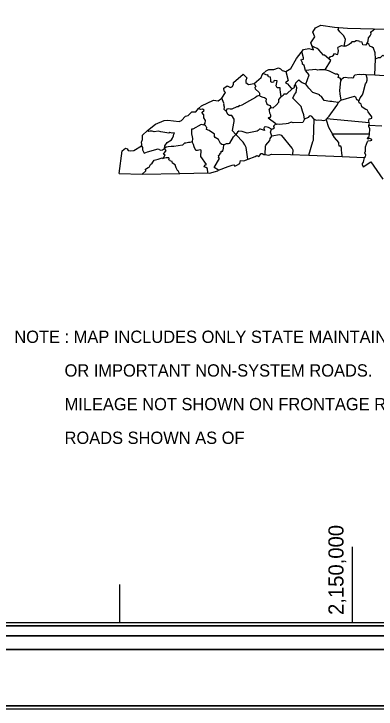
# Model space of a CAD drawing. Extents: x 5197761 to 5514561, y 1890130 to 2080942.
# Drawn here: x 5366240 to 5381799, y 1890130 to 1920005 of the extents above; entities that cross this region are included whole.
import ezdxf

# ---------------------------------------------------------------- set-up
doc = ezdxf.new("R2010")
doc.units = 0
for name, color, linetype in [('Map Preparation Base Location CELL', 7, 'Continuous'), ('Map Preparation Base Note CELL', 7, 'Continuous'), ('Map Preparation Base StatePlane Tick Label', 7, 'Continuous'), ('Map Preparation Base StatePlane Tick Mark', 7, 'Continuous'), ('Map Preparation Border Antique Large Shape', 7, 'Continuous'), ('Map Preparation Border Antique Small Shape', 7, 'Continuous'), ('Map Preparation Border Black Inside Shape', 7, 'Continuous'), ('Map Preparation Border Black Middle Shape', 7, 'Continuous'), ('Map Preparation Border Black Outside Shape', 7, 'Continuous')]:
    doc.layers.add(name, color=color, linetype=linetype)

msp = doc.modelspace()

# ---------------------------------------------------------------- linework, layer by layer
at = {"layer": 'Map Preparation Base Location CELL'}
for p, q in [((5379605, 1917603), (5379848, 1918008)), ((5379848, 1918008), (5379766, 1918070)), ((5381750, 1917370), (5381374, 1917386)), ((5380190, 1916200), (5380283, 1916298)), ((5379651, 1915448), (5379672, 1915498)), ((5381508, 1915324), (5379672, 1915498)), ((5382052, 1915179), (5381491, 1915215)), ((5381510, 1914842), (5379926, 1914837))]:
    msp.add_line(p, q, dxfattribs=at)
for points in [[(5370768, 1913142), (5370889, 1914119), (5371028, 1914231), (5371106, 1914204), (5371152, 1914141), (5371253, 1914120), (5371390, 1914139), (5371715, 1914331), (5371715, 1914331), (5371741, 1914395), (5371716, 1914486), (5371769, 1914606), (5371764, 1914789), (5371974, 1915000), (5372320, 1915270), (5372697, 1915427), (5372849, 1915443), (5373340, 1915383), (5373442, 1915427), (5373610, 1915610), (5373728, 1915643), (5373880, 1915794), (5374058, 1915799), (5374176, 1915940), (5374301, 1916048), (5374813, 1916291), (5375013, 1916269), (5375170, 1916377), (5375332, 1916626), (5375272, 1916688), (5375262, 1916818), (5375396, 1916915), (5375542, 1916839), (5375629, 1916888), (5375677, 1916980), (5375677, 1917061), (5376090, 1917412), (5376252, 1917255), (5376203, 1917147), (5376208, 1917050), (5376316, 1916974), (5376565, 1917012), (5376856, 1917277), (5376905, 1917390), (5376953, 1917450), (5377072, 1917563), (5377185, 1917612), (5377407, 1917617), (5377601, 1917682), (5377698, 1917639), (5377758, 1917568), (5377920, 1917531), (5378141, 1917660), (5378373, 1918092), (5378675, 1918481), (5378913, 1918524), (5379107, 1918460), (5378999, 1918762), (5379172, 1919021), (5379086, 1919216), (5379193, 1919410), (5379431, 1919518), (5380014, 1919432), (5380575, 1919389), (5384470, 1919293)], [(5380430, 1918621), (5380482, 1918902), (5380414, 1919061), (5380243, 1919230), (5380166, 1919332), (5380202, 1919417)], [(5381417, 1918753), (5381463, 1918841), (5381470, 1918975), (5381543, 1919059), (5381592, 1919142), (5381579, 1919203), (5381599, 1919245), (5381742, 1919360)], [(5379766, 1918070), (5379588, 1918226), (5379535, 1918238), (5379344, 1918460), (5379270, 1918520), (5379133, 1918580), (5379043, 1918639)], [(5379766, 1918070), (5379846, 1918180), (5379907, 1918189), (5379967, 1918225), (5380019, 1918298), (5380120, 1918266), (5380153, 1918274), (5380176, 1918334), (5380181, 1918428), (5380158, 1918553), (5380166, 1918574), (5380315, 1918651), (5380430, 1918621)], [(5381417, 1918753), (5381338, 1918657), (5381225, 1918669), (5381203, 1918794), (5381091, 1918807), (5381066, 1918828), (5380982, 1918845), (5380936, 1918843), (5380878, 1918798), (5380752, 1918808), (5380715, 1918750), (5380637, 1918685), (5380498, 1918620), (5380430, 1918621)], [(5381769, 1918078), (5381763, 1918331), (5381693, 1918526), (5381624, 1918582), (5381524, 1918615), (5381483, 1918707), (5381417, 1918753)], [(5378765, 1917567), (5378709, 1917781), (5378640, 1917840), (5378641, 1917908), (5378578, 1918011), (5378600, 1918062), (5378633, 1918044), (5378677, 1918060), (5378676, 1918114), (5378604, 1918389)], [(5381750, 1917370), (5381769, 1918078)], [(5381769, 1918078), (5381906, 1918133), (5381993, 1918129), (5382092, 1918236), (5382103, 1918220), (5382177, 1918195), (5382348, 1918178), (5382435, 1918147), (5382556, 1918250), (5382600, 1918234), (5382647, 1918213), (5382800, 1918225), (5382843, 1918210), (5382878, 1918168), (5382922, 1918157), (5383003, 1918153), (5383060, 1918135), (5383128, 1918075)], [(5378211, 1916798), (5377950, 1916561), (5377830, 1916551), (5377809, 1916500), (5377723, 1916436), (5377704, 1916528), (5377699, 1916650), (5377685, 1916746), (5377684, 1916831), (5377552, 1916831), (5377513, 1916908), (5377544, 1917128), (5377455, 1917140), (5377408, 1917129), (5377396, 1917077), (5377335, 1917063), (5377283, 1917083), (5377278, 1917174), (5377262, 1917288), (5377173, 1917305), (5377144, 1917389), (5377101, 1917373), (5376954, 1917450)], [(5377921, 1917532), (5378019, 1917138), (5377905, 1917042), (5377995, 1917003), (5378139, 1916835), (5378211, 1916798)], [(5379605, 1917603), (5379372, 1917601), (5379275, 1917593), (5379209, 1917615), (5378765, 1917567)], [(5378776, 1916991), (5378930, 1917391), (5378765, 1917567)], [(5380293, 1917175), (5380261, 1917238), (5380167, 1917279), (5380193, 1917360), (5380128, 1917410), (5380052, 1917421), (5379796, 1917544), (5379605, 1917603)], [(5381374, 1917386), (5381259, 1917408), (5381164, 1917387), (5381075, 1917404), (5380883, 1917370), (5380846, 1917335), (5380819, 1917250), (5380799, 1917239), (5380737, 1917253), (5380632, 1917250), (5380498, 1917270), (5380405, 1917253), (5380293, 1917175), (5380273, 1917133), (5380232, 1916713), (5380242, 1916573), (5380283, 1916298)], [(5378333, 1916978), (5378347, 1917047), (5378484, 1917176), (5378575, 1917082), (5378626, 1917053), (5378776, 1916991)], [(5381052, 1916251), (5381115, 1916394), (5381209, 1916527), (5381248, 1916607), (5381346, 1917004), (5381382, 1917057), (5381412, 1917161), (5381416, 1917250), (5381374, 1917386)], [(5382365, 1917334), (5381750, 1917370)], [(5376566, 1917013), (5376637, 1916885), (5376595, 1916846), (5376597, 1916792), (5376778, 1916629), (5376797, 1916599), (5376791, 1916493)], [(5378211, 1916798), (5378290, 1916840), (5378291, 1916907), (5378333, 1916978)], [(5378718, 1915479), (5378695, 1915661), (5378634, 1915830), (5378577, 1916031), (5378229, 1916388), (5378300, 1916535), (5378363, 1916624), (5378401, 1916825), (5378333, 1916978)], [(5380190, 1916200), (5379967, 1916224), (5379902, 1916242), (5379811, 1916246), (5379562, 1916283), (5379448, 1916460), (5379372, 1916498), (5379375, 1916520), (5379087, 1916633), (5378905, 1916816), (5378776, 1916991)], [(5376791, 1916493), (5376693, 1916475), (5376612, 1916410), (5376361, 1916269), (5376032, 1916090), (5375964, 1916055), (5375920, 1916065), (5375867, 1916005), (5375822, 1916011), (5375600, 1915907), (5375532, 1915907), (5375466, 1915924), (5375382, 1915904), (5375361, 1915844)], [(5376791, 1916493), (5376814, 1916463), (5376935, 1916420), (5377008, 1916419), (5377045, 1916391), (5377075, 1916351), (5377066, 1916254), (5377106, 1916146), (5377158, 1916103), (5377244, 1916065), (5377273, 1915985)], [(5375361, 1915844), (5375296, 1915866), (5375272, 1915892), (5375281, 1915997), (5375254, 1916095), (5375269, 1916137), (5375264, 1916174), (5375174, 1916383)], [(5377273, 1915985), (5377375, 1915966), (5377508, 1916077), (5377623, 1916213)], [(5377623, 1916213), (5377616, 1916326), (5377723, 1916436)], [(5379672, 1915498), (5379784, 1915611), (5380112, 1916068), (5380190, 1916200)], [(5380283, 1916298), (5380877, 1916470), (5380919, 1916446), (5380956, 1916333), (5380994, 1916313), (5381052, 1916251)], [(5381508, 1915324), (5381491, 1915416), (5381507, 1915494), (5381567, 1915503), (5381615, 1915518), (5381617, 1915584), (5381463, 1915791), (5381422, 1915878), (5381356, 1915892), (5381240, 1915968), (5381193, 1916011), (5381155, 1916119), (5381075, 1916189), (5381052, 1916251)], [(5374397, 1915230), (5374457, 1915307), (5374477, 1915424), (5374402, 1915541), (5374401, 1915674), (5374319, 1915774), (5374346, 1915802), (5374405, 1915843), (5374413, 1915865), (5374341, 1915905), (5374254, 1915898), (5374168, 1915933)], [(5377496, 1915285), (5377168, 1915531), (5377198, 1915549), (5377244, 1915551), (5377281, 1915591), (5377280, 1915649), (5377230, 1915741), (5377213, 1915850), (5377200, 1915883), (5377273, 1915985)], [(5375779, 1914828), (5375624, 1914986), (5375642, 1915081), (5375705, 1915385), (5375695, 1915475), (5375595, 1915640), (5375505, 1915643), (5375424, 1915676), (5375361, 1915844)], [(5379144, 1915481), (5379038, 1915590), (5378983, 1915620), (5378923, 1915611), (5378883, 1915549), (5378718, 1915479)], [(5378718, 1915479), (5378657, 1915341), (5378234, 1915325), (5378144, 1915355), (5378017, 1915293), (5377938, 1915277), (5377774, 1915273), (5377644, 1915247), (5377583, 1915260), (5377522, 1915255), (5377496, 1915285)], [(5378909, 1913938), (5379079, 1914519), (5379107, 1914582), (5379144, 1915481)], [(5379144, 1915481), (5379228, 1915433), (5379342, 1915453), (5379465, 1915443), (5379543, 1915430), (5379651, 1915448)], [(5379651, 1915448), (5379754, 1915138), (5379865, 1914939), (5379926, 1914837)], [(5381491, 1915215), (5381512, 1915292), (5381508, 1915324)], [(5374397, 1915230), (5374287, 1915253), (5373932, 1915058), (5373869, 1915052), (5373865, 1914853), (5373903, 1914728), (5373916, 1914655), (5373902, 1914506)], [(5375257, 1914372), (5375178, 1914387), (5375117, 1914430), (5375032, 1914610), (5374891, 1914699), (5374860, 1914739), (5374855, 1914833), (5374624, 1915001), (5374516, 1915032), (5374527, 1915120), (5374499, 1915146), (5374475, 1915206), (5374397, 1915230)], [(5377305, 1915057), (5377171, 1915129), (5377069, 1915148), (5376995, 1915135), (5376975, 1915085), (5376992, 1915047), (5376999, 1914997), (5376834, 1915051), (5376789, 1915048), (5376740, 1914988), (5376691, 1914963), (5376264, 1914878), (5376049, 1914956), (5375907, 1914971), (5375841, 1914917), (5375779, 1914828)], [(5377315, 1914745), (5377272, 1914884), (5377269, 1914929), (5377305, 1915057)], [(5377305, 1915057), (5377360, 1915059), (5377432, 1915124), (5377411, 1915167), (5377411, 1915199), (5377496, 1915285)], [(5381510, 1914842), (5381532, 1915070), (5381493, 1915170), (5381491, 1915215)], [(5372704, 1914221), (5372724, 1914342), (5372817, 1914473), (5373003, 1914592), (5373052, 1914661), (5373101, 1914762), (5373110, 1914832), (5373144, 1914890), (5373136, 1914900), (5373039, 1914876), (5372939, 1914911), (5372891, 1914885), (5372546, 1914937), (5372451, 1914966), (5372262, 1914940), (5372175, 1914964), (5372094, 1914965), (5372039, 1914958), (5371958, 1914987)], [(5375257, 1914372), (5375370, 1914437), (5375465, 1914438), (5375512, 1914454), (5375670, 1914722), (5375779, 1914828)], [(5376290, 1913758), (5376215, 1914258), (5376160, 1914381), (5376085, 1914493), (5375779, 1914828)], [(5377029, 1913963), (5377048, 1914323), (5377068, 1914365), (5377227, 1914570), (5377252, 1914647), (5377315, 1914745)], [(5378227, 1913960), (5378241, 1914153), (5378199, 1914239), (5377744, 1914774), (5377644, 1914801), (5377315, 1914745)], [(5380344, 1913870), (5380328, 1914061), (5380306, 1914122), (5380309, 1914233), (5380277, 1914318), (5380218, 1914318), (5380204, 1914431), (5380203, 1914485), (5380018, 1914699), (5379926, 1914837)], [(5381292, 1913832), (5381338, 1913880), (5381359, 1913930), (5381320, 1914029), (5381345, 1914101), (5381343, 1914292), (5381433, 1914519), (5381465, 1914550), (5381580, 1914564), (5381609, 1914577), (5381614, 1914608), (5381560, 1914643), (5381507, 1914651), (5381458, 1914627), (5381436, 1914657), (5381445, 1914687), (5381497, 1914732), (5381510, 1914842)], [(5373902, 1914506), (5373794, 1914476), (5373736, 1914483), (5373621, 1914457), (5373562, 1914456), (5373477, 1914360), (5373115, 1914303), (5372994, 1914309), (5372861, 1914286), (5372783, 1914277), (5372704, 1914221)], [(5374568, 1913172), (5374553, 1913364), (5374482, 1913409), (5374434, 1913415), (5374412, 1913453), (5374464, 1913513), (5374513, 1913538), (5374265, 1913879), (5374279, 1914152), (5374244, 1914161), (5374123, 1914132), (5374056, 1914136), (5373977, 1914288), (5373954, 1914393), (5373902, 1914506)], [(5371715, 1914331), (5371769, 1914258), (5371761, 1914157), (5371835, 1914025), (5371977, 1914083), (5372433, 1914209), (5372538, 1914152), (5372617, 1914169), (5372704, 1914221)], [(5372651, 1913798), (5372732, 1913943), (5372684, 1913957), (5372664, 1913973), (5372774, 1914132), (5372704, 1914221)], [(5375027, 1913290), (5374841, 1913411), (5375066, 1913785), (5375035, 1913820), (5375037, 1913864), (5375022, 1913924), (5375070, 1913948), (5375116, 1914022), (5375139, 1914028), (5375146, 1914111), (5375212, 1914103), (5375244, 1914241), (5375257, 1914372)], [(5370768, 1913142), (5371746, 1913115), (5373368, 1913153), (5374568, 1913172), (5374641, 1913154), (5374996, 1913265), (5375027, 1913290), (5375450, 1913453), (5375619, 1913509), (5375683, 1913517), (5375735, 1913468), (5375818, 1913505), (5375946, 1913581), (5375976, 1913705), (5376122, 1913686), (5376306, 1913765), (5376599, 1913877), (5376674, 1913922), (5376764, 1913881), (5376862, 1914001), (5376911, 1914009), (5376978, 1913964), (5377020, 1913964), (5377196, 1913941), (5377312, 1913983), (5378120, 1913964), (5378909, 1913937), (5380340, 1913870), (5381291, 1913829), (5381239, 1913629), (5381197, 1913573), (5381194, 1913528), (5381250, 1913438), (5381573, 1913641), (5382087, 1912908)], [(5371746, 1913115), (5371903, 1913260), (5371898, 1913336), (5372011, 1913411), (5372048, 1913424), (5372106, 1913527), (5372176, 1913585), (5372260, 1913726), (5372431, 1913758), (5372604, 1913817), (5372651, 1913798)], [(5373359, 1913153), (5373301, 1913262), (5373268, 1913279), (5373205, 1913389), (5373172, 1913517), (5373047, 1913594), (5373034, 1913662), (5372968, 1913675), (5372950, 1913708), (5372898, 1913727), (5372911, 1913792), (5372893, 1913825), (5372775, 1913822), (5372651, 1913798)]]:
    msp.add_lwpolyline(points, dxfattribs=at)
at = {"layer": 'Map Preparation Base StatePlane Tick Mark'}
for p, q in [((5380787, 1893858), (5380787, 1897109)), ((5370787, 1893858), (5370787, 1895484))]:
    msp.add_line(p, q, dxfattribs=at)
at = {"layer": 'Map Preparation Border Antique Large Shape'}
msp.add_lwpolyline([(5197907, 2074783), (5207205, 2074783), (5207205, 1892697), (5512539, 1892697), (5512539, 2072359), (5207205, 2072359), (5207205, 2074783), (5514414, 2074783), (5514414, 1890276), (5197907, 1890276)], close=True, dxfattribs=at)
at = {"layer": 'Map Preparation Border Antique Small Shape'}
msp.add_lwpolyline([(5207791, 2071720), (5208220, 2071720), (5208220, 1893712), (5511524, 1893712), (5511524, 2071291), (5208220, 2071291), (5208220, 2071720), (5207791, 2071720), (5511953, 2071720), (5511953, 1893283), (5208220, 1893283), (5207791, 1893283)], close=True, dxfattribs=at)
at = {"layer": 'Map Preparation Border Black Inside Shape'}
msp.add_lwpolyline([(5208220, 2071291), (5511524, 2071291), (5511524, 1893712), (5208366, 1893712), (5208366, 1893858), (5511378, 1893858), (5511378, 2071145), (5208366, 2071145), (5208366, 1893858), (5208366, 1893712), (5208220, 1893712), (5208220, 1893858)], close=True, dxfattribs=at)
at = {"layer": 'Map Preparation Border Black Middle Shape'}
msp.add_lwpolyline([(5207205, 2072359), (5512539, 2072359), (5512539, 1892697), (5511953, 1892697), (5207791, 1892697), (5207791, 1893283), (5511953, 1893283), (5511953, 2071720), (5207791, 2071720), (5207791, 1892697), (5207205, 1892697)], close=True, dxfattribs=at)
at = {"layer": 'Map Preparation Border Black Outside Shape'}
msp.add_lwpolyline([(5197761, 2074930), (5514561, 2074930), (5514561, 1890130), (5197907, 1890130), (5197907, 1890276), (5514414, 1890276), (5514414, 2074783), (5197907, 2074783), (5197907, 1890130), (5197761, 1890130)], close=True, dxfattribs=at)

# ---------------------------------------------------------------- texts
at = {"layer": 'Map Preparation Base Note CELL'}
for s, p in [('NOTE : MAP INCLUDES ONLY STATE MAINTAINED ROADS', (5366257, 1905866)), ('           OR IMPORTANT NON-SYSTEM ROADS.', (5366257, 1904419)), ('           MILEAGE NOT SHOWN ON FRONTAGE ROADS.', (5366257, 1902972)), ('           ROADS SHOWN AS OF                ', (5366257, 1901525))]:
    msp.add_text(s, height=528.21, dxfattribs=at).set_placement(p)
at = {"layer": 'Map Preparation Base StatePlane Tick Label'}
msp.add_text('2,150,000', height=650, rotation=90, dxfattribs=at).set_placement((5380400, 1894176))

doc.saveas('drawing.dxf')
